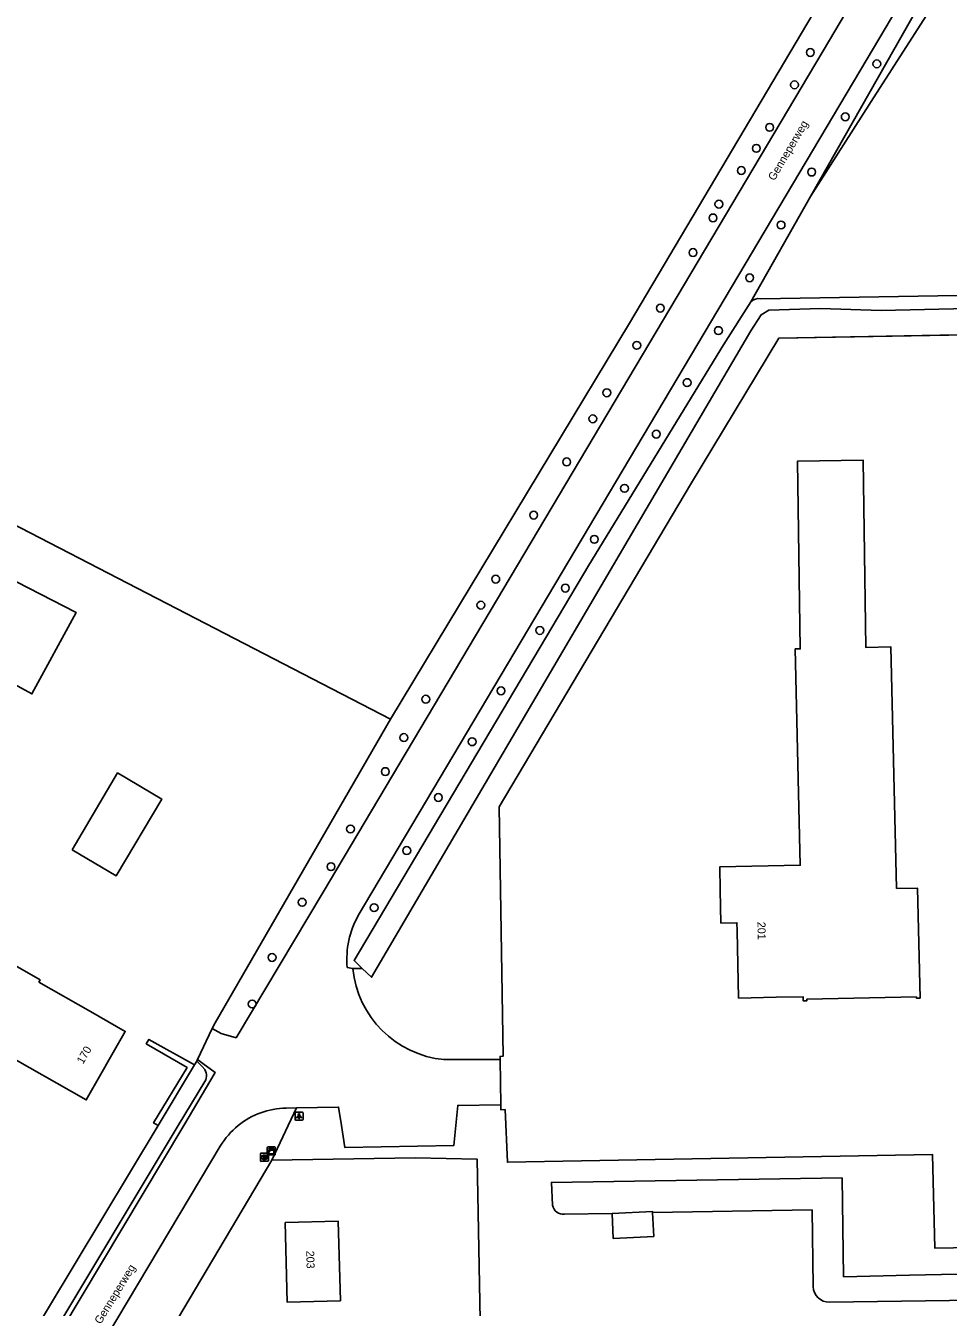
# Model space of a CAD drawing. Extents: x 160203 to 161526, y 379529 to 381797.
# Drawn here: x 160351.6 to 160466.9, y 379977.3 to 380137.4 of the extents above; entities that cross this region are included whole.
import ezdxf

# ---------------------------------------------------------------- set-up
doc = ezdxf.new("R2010")
doc.units = 0
for name, color, linetype in [('IMGEO_Berm_groen', 7, 'Continuous'), ('IMGEO_Boom', 7, 'Continuous'), ('IMGEO_Bouwland', 7, 'Continuous'), ('IMGEO_Grasland_agrarisch', 7, 'Continuous'), ('IMGEO_Grasland_overig', 7, 'Continuous'), ('IMGEO_Groenvoorziening', 7, 'Continuous'), ('IMGEO_Haag', 7, 'Continuous'), ('IMGEO_Hek', 7, 'Continuous'), ('IMGEO_Kast', 7, 'Continuous'), ('IMGEO_Lichtpunt', 7, 'Continuous'), ('IMGEO_Openbare_ruimte_label', 7, 'Continuous'), ('IMGEO_Pand', 7, 'Continuous'), ('IMGEO_Pand_nummerreeks', 7, 'Continuous'), ('IMGEO_Rijbaan_lokaal_open', 7, 'Continuous'), ('IMGEO_Rioolput', 7, 'Continuous'), ('IMGEO_Waterloop', 7, 'Continuous')]:
    doc.layers.add(name, color=color, linetype=linetype)

msp = doc.modelspace()

# ---------------------------------------------------------------- linework, layer by layer
at = {"layer": 'IMGEO_Berm_groen'}
for points in [[(160373.06, 380008.26), (160372.96, 380008.04)], [(160382.33, 379995.65), (160385.42, 380002.19)], [(160360.33, 379958.58), (160382.33, 379995.65)]]:
    msp.add_lwpolyline(points, dxfattribs=at)
at = {"layer": 'IMGEO_Boom'}
for centre in [(160449.64, 380134.09), (160457.95, 380132.66), (160447.66, 380130.04), (160454, 380126.05), (160444.56, 380124.73), (160442.89, 380122.1), (160441.01, 380119.33), (160449.81, 380119.14), (160438.21, 380115.13), (160437.47, 380113.41), (160445.98, 380112.53), (160434.98, 380109.08), (160442.05, 380105.93), (160430.89, 380102.14), (160438.15, 380099.33), (160427.95, 380097.48), (160434.24, 380092.83), (160424.2, 380091.56), (160422.45, 380088.31), (160430.38, 380086.39), (160419.19, 380082.92), (160426.41, 380079.61), (160415.06, 380076.27), (160422.64, 380073.24), (160410.32, 380068.27), (160419.01, 380067.15), (160408.46, 380065.02), (160415.83, 380061.86), (160401.58, 380053.26), (160410.98, 380054.31), (160398.84, 380048.47), (160407.37, 380047.95), (160396.52, 380044.22), (160403.14, 380040.98), (160392.17, 380037.05), (160399.2, 380034.35), (160389.73, 380032.34), (160386.13, 380027.89), (160395.12, 380027.22), (160382.37, 380020.99), (160379.88, 380015.17)]:
    msp.add_circle(centre, 0.489, dxfattribs=at)
at = {"layer": 'IMGEO_Bouwland'}
msp.add_lwpolyline([(160442.2, 380102.92), (160449.65, 380116.07)], dxfattribs=at)
at = {"layer": 'IMGEO_Grasland_agrarisch'}
for points in [[(160457.16, 380151.09), (160427.02, 380100.25), (160397.18, 380050.75)], [(160397.18, 380050.75), (160349.7, 380075.29)]]:
    msp.add_lwpolyline(points, dxfattribs=at)
at = {"layer": 'IMGEO_Grasland_overig'}
for points in [[(160449.65, 380116.07), (160457.26, 380127.95), (160486.32, 380173.3), (160489.77, 380174.54)], [(160449.65, 380116.07), (160465.43, 380143.93), (160472.15, 380155.79)], [(160497.32, 380099.25), (160500, 380099.36), (160552.52, 380100.27), (160568.93, 380078.16), (160570.15, 380000), (160570.38, 379986.91), (160500, 379985.28), (160465.21, 379984.65), (160464.91, 379996.35), (160411.77, 379995.39), (160411.48, 380001.98), (160410.95, 380001.97), (160410.94, 380002.59)], [(160410.88, 380008.24), (160410.87, 380008.63), (160411.24, 380008.64), (160410.76, 380039.8), (160434.65, 380080.09), (160445.7, 380098.4), (160492.69, 380099.27)], [(160392.47, 380019.6), (160393.64, 380019.61)], [(160368.22, 379945.15), (160400.15, 379946.25), (160408.91, 379946.67), (160407.99, 379995.8), (160400.24, 379995.97), (160382.33, 379995.65)]]:
    msp.add_lwpolyline(points, dxfattribs=at)
at = {"layer": 'IMGEO_Groenvoorziening'}
msp.add_lwpolyline([(160397.18, 380050.75), (160375.24, 380012.84), (160374.9, 380012.13)], dxfattribs=at)
at = {"layer": 'IMGEO_Haag'}
msp.add_lwpolyline([(160368.12, 380000), (160367.56, 380000.32), (160371.74, 380007.24), (160366.65, 380010.21), (160366.97, 380010.76), (160372.68, 380007.58)], dxfattribs=at)
at = {"layer": 'IMGEO_Hek'}
for points in [[(160500, 380099.36), (160445.7, 380098.4)], [(160445.7, 380098.4), (160434.65, 380080.09), (160410.76, 380039.8), (160411.24, 380008.64)], [(160397.18, 380050.75), (160349.7, 380075.29)], [(160411.48, 380001.98), (160411.77, 379995.39)], [(160411.77, 379995.39), (160464.91, 379996.35), (160465.21, 379984.65), (160500, 379985.28)]]:
    msp.add_lwpolyline(points, dxfattribs=at)
at = {"layer": 'IMGEO_Kast'}
for p, q in [((160381.77, 379996.39), (160381.77, 379997.23)), ((160381.77, 379997.23), (160381.77, 379996.39)), ((160381.85, 379997.31), (160382.69, 379997.31)), ((160382.69, 379997.31), (160381.85, 379997.31)), ((160382.7, 379996.31), (160381.86, 379996.31)), ((160381.86, 379996.31), (160382.7, 379996.31)), ((160382.77, 379997.24), (160382.77, 379996.4)), ((160382.77, 379996.4), (160382.77, 379997.24))]:
    msp.add_line(p, q, dxfattribs=at)
for points in [[(160381.97, 379997.1), (160382.57, 379997.1), (160382.57, 379997.02), (160381.97, 379997.02), (160381.97, 379997.1)], [(160381.97, 379996.93), (160382.57, 379996.93), (160382.57, 379996.44), (160381.97, 379996.44), (160381.97, 379996.93)]]:
    msp.add_lwpolyline(points, dxfattribs=at)
msp.add_circle((160382.05, 379996.78), 0.0377, dxfattribs=at)
for centre, start, end in [((160381.85, 379997.24), 92.4484, 184.2845), ((160381.85, 379997.24), 92.4484, 184.2845), ((160381.85, 379996.39), 182.4484, 274.2845), ((160381.85, 379996.39), 182.4484, 274.2845), ((160382.69, 379997.24), 2.4484, 94.2845), ((160382.69, 379997.24), 2.4484, 94.2845), ((160382.69, 379996.39), 272.4484, 4.2845), ((160382.69, 379996.39), 272.4484, 4.2845)]:
    msp.add_arc(centre, 0.0779, start, end, dxfattribs=at)
at = {"layer": 'IMGEO_Lichtpunt'}
for p, q in [((160385.24, 380001.56), (160385.24, 380000.75)), ((160385.24, 380001.56), (160385.24, 380000.75)), ((160386.14, 380001.65), (160385.34, 380001.65)), ((160386.14, 380001.65), (160385.34, 380001.65)), ((160386.24, 380000.75), (160386.24, 380001.56)), ((160386.24, 380000.75), (160386.24, 380001.56)), ((160385.34, 380000.66), (160386.14, 380000.66)), ((160385.34, 380000.66), (160386.14, 380000.66))]:
    msp.add_line(p, q, dxfattribs=at)
for points in [[(160385.62, 380001.22), (160385.65, 380001.19), (160385.47, 380000.93), (160385.43, 380000.96), (160385.62, 380001.22)], [(160385.72, 380001.17), (160385.76, 380001.17), (160385.76, 380000.85), (160385.72, 380000.85), (160385.72, 380001.17)], [(160385.83, 380001.19), (160385.87, 380001.22), (160386.05, 380000.96), (160386.01, 380000.93), (160385.83, 380001.19)]]:
    msp.add_lwpolyline(points, dxfattribs=at)
msp.add_circle((160385.74, 380001.36), 0.0994, dxfattribs=at)
for centre, start, end in [((160385.34, 380001.56), 90, 180), ((160385.34, 380001.56), 90, 180), ((160386.14, 380001.56), 0, 90), ((160386.14, 380001.56), 0, 90), ((160385.34, 380000.75), 180, 270), ((160385.34, 380000.75), 180, 270), ((160386.14, 380000.75), 270, 0), ((160386.14, 380000.75), 270, 360)]:
    msp.add_arc(centre, 0.0946, start, end, dxfattribs=at)
at = {"layer": 'IMGEO_Pand'}
for points in [[(160460.39, 380029.6), (160463.04, 380029.65), (160463.35, 380015.92), (160462.89, 380015.91), (160462.89, 380016.07), (160449.18, 380015.77), (160449.19, 380015.57), (160448.75, 380015.56), (160448.74, 380016.09), (160445.35, 380016.01), (160440.68, 380015.91), (160440.49, 380024.3), (160440.47, 380025.32), (160438.47, 380025.28), (160438.37, 380029.41), (160438.31, 380032.3), (160448.37, 380032.52), (160447.76, 380059.54), (160448.38, 380059.55), (160448.05, 380083.02), (160456.23, 380083.14), (160456.56, 380059.73), (160459.71, 380059.8), (160460.39, 380029.6)], [(160343.54, 380058.71), (160348.96, 380068.69), (160357.89, 380064.08), (160352.36, 380053.92), (160343.54, 380058.71)], [(160357.37, 380034.45), (160363.05, 380044.05), (160368.57, 380040.78), (160362.88, 380031.19), (160357.37, 380034.45)], [(160353.21, 380017.9), (160353.37, 380018.19), (160345.85, 380022.48), (160340.67, 380025.43), (160335.52, 380028.43), (160333.9, 380025.59), (160330.26, 380019.22), (160334.94, 380016.55), (160333.95, 380014.81), (160332.42, 380015.68), (160331.47, 380014.01), (160343.62, 380007.08), (160346.29, 380005.56), (160348.42, 380009.29), (160359.14, 380003.18), (160364.02, 380011.74), (160359.68, 380014.22), (160353.21, 380017.9)], [(160390.9, 379978.09), (160384.27, 379977.91), (160384.01, 379987.85), (160390.64, 379988.02), (160390.9, 379978.09)], [(160424.87, 379989), (160429.92, 379989.24), (160429.93, 379989.1)], [(160429.93, 379989.1), (160430.07, 379986.13), (160425.01, 379985.89), (160424.87, 379989)]]:
    msp.add_lwpolyline(points, dxfattribs=at)
at = {"layer": 'IMGEO_Rijbaan_lokaal_open'}
for points in [[(160457.51, 380144.89), (160452.03, 380135.62), (160388.75, 380029.17), (160377.87, 380010.95), (160375.99, 380011.51), (160374.9, 380012.13)], [(160462.03, 380142.26), (160456.74, 380133.28), (160393.14, 380026.24)], [(160391.75, 380019.75), (160392.47, 380019.6)], [(160374.9, 380012.13), (160373.06, 380008.26)], [(160353.43, 379970.05), (160371.33, 380000), (160375.27, 380006.61), (160373.71, 380007.73), (160373.06, 380008.26)], [(160410.88, 380008.24), (160403.85, 380008.23)], [(160410.94, 380002.59), (160410.88, 380008.24)], [(160385.42, 380002.19), (160390.68, 380002.3), (160391.04, 380000), (160391.47, 379997.23), (160405.09, 379997.51), (160405.33, 380000), (160405.58, 380002.5), (160410.94, 380002.59)], [(160385.42, 380002.19), (160384.12, 380002.17)], [(160375.89, 379997.42), (160357.91, 379967.3)]]:
    msp.add_lwpolyline(points, dxfattribs=at)
for centre, radius, start, end in [((160402.99, 380020.75), 11.28, 150.8511, 185.0979), ((160405.04, 380020.8), 12.63, 185.4693, 264.6113), ((160384.29, 379992.35), 9.82, 91.0157, 128.8336), ((160384.33, 379992.35), 9.84, 129.0059, 149.0134)]:
    msp.add_arc(centre, radius, start, end, dxfattribs=at)
at = {"layer": 'IMGEO_Rioolput'}
for p, q in [((160380.91, 379995.59), (160380.91, 379996.44)), ((160380.98, 379996.52), (160381.84, 379996.52)), ((160381.4, 379996.3), (160381.42, 379996.3)), ((160381.91, 379996.44), (160381.91, 379995.59)), ((160381.84, 379995.52), (160380.98, 379995.52)), ((160381.42, 379995.74), (160381.4, 379995.74))]:
    msp.add_line(p, q, dxfattribs=at)
for points in [[(160380.91, 379995.59), (160380.91, 379996.44)], [(160380.98, 379996.52), (160381.84, 379996.52)], [(160381.5, 379996.21), (160381.25, 379996.22), (160381.25, 379995.82)], [(160381.43, 379996.14), (160381.37, 379996.14), (160381.37, 379996.05)], [(160381.37, 379996.05), (160381.42, 379996.05)], [(160381.91, 379996.44), (160381.91, 379995.59)], [(160381.84, 379995.52), (160380.98, 379995.52)], [(160381.25, 379995.82), (160381.37, 379995.82), (160381.37, 379995.98), (160381.38, 379995.98)], [(160381.43, 379995.95), (160381.5, 379995.82), (160381.64, 379995.82), (160381.57, 379995.94)]]:
    msp.add_lwpolyline(points, dxfattribs=at)
for centre, radius, start, end in [((160380.99, 379996.44), 0.0765, 91.552, 178.448), ((160380.99, 379996.44), 0.0765, 91.552, 178.448), ((160381.41, 379996.24), 0.19, 274.7715, 282.9687), ((160381.43, 379996.04), 0.0964, 77.0061, 93.1865), ((160381.45, 379996.1), 0.0378, 276.6634, 79.6772), ((160381.5, 379996.11), 0.109, 350.3612, 89.416), ((160381.5, 379996.1), 0.112, 277.5842, 350.9817), ((160381.83, 379996.44), 0.0765, 1.552, 88.448), ((160381.83, 379996.44), 0.0765, 1.552, 88.448), ((160380.99, 379995.59), 0.0765, 181.552, 268.448), ((160380.99, 379995.59), 0.0765, 181.552, 268.448), ((160381.38, 379995.93), 0.0533, 26.0293, 88.6989), ((160381.48, 379995.89), 0.108, 29.5134, 73.7905), ((160381.83, 379995.59), 0.0765, 271.552, 358.448), ((160381.83, 379995.59), 0.0765, 271.552, 358.448)]:
    msp.add_arc(centre, radius, start, end, dxfattribs=at)
for centre, major_axis, ratio, start_param, end_param in [((160381.4, 379996.02), (-0.387, 0.002), 0.722429, 4.712389, 7.853982), ((160381.42, 379996.02), (-0.39, 0.002), 0.717154, 1.570796, 4.712389)]:
    msp.add_ellipse(centre, major_axis=major_axis, ratio=ratio, start_param=start_param, end_param=end_param, dxfattribs=at)
at = {"layer": 'IMGEO_Waterloop'}
for points in [[(160552.79, 380106.07), (160552.5, 380105.98), (160542.34, 380104.96), (160500, 380104.25), (160443.43, 380103.3)], [(160572.68, 380044.44), (160571.3, 380082.02), (160570.87, 380083.04), (160564.09, 380090.73), (160556.2, 380100.44), (160553.48, 380103.35), (160548.27, 380103.87), (160500, 380102.78), (160458.47, 380101.85), (160450.92, 380102.08), (160444.44, 380101.9), (160443.49, 380101.31), (160442.22, 380099.32), (160394.8, 380018.51), (160393.64, 380019.61)], [(160393.64, 380019.61), (160392.61, 380020.6), (160421.94, 380070), (160438.79, 380097.57), (160442.2, 380102.92)], [(160417.41, 379990.03), (160417.28, 379992.88), (160453.6, 379993.44), (160453.79, 379981.09), (160462.01, 379981.27), (160500, 379982.1), (160572.95, 379983.71), (160572.74, 380000), (160572.54, 380019.05), (160573.09, 380019.94), (160574.06, 380020.32), (160587.13, 380020.56)], [(160372.68, 380007.58), (160368.12, 380000)], [(160372.96, 380008.04), (160372.68, 380007.58)], [(160372.96, 380008.04), (160373.8, 380007.18)], [(160373.96, 380005.5), (160370.65, 380000), (160353.95, 379972.21)], [(160368.12, 380000), (160350.83, 379971.26), (160350.52, 379971.11), (160350.09, 379971.23), (160347.92, 379974.93), (160340.63, 379986.39), (160337.45, 379991.38)], [(160424.87, 379989), (160418.92, 379988.92)], [(160450, 379979.87), (160449.85, 379989.44), (160429.93, 379989.1)], [(160576.07, 379979.7), (160500, 379978.6), (160458.03, 379977.99), (160452.03, 379977.91)]]:
    msp.add_lwpolyline(points, dxfattribs=at)
for centre, radius, start, end in [((160443.18, 380101.96), 1.37, 79.4379, 135.4881), ((160372.9, 380006.25), 1.29, 324.7863, 45.9847), ((160418.76, 379990.27), 1.37, 190.2348, 277.0146), ((160452, 379979.91), 2, 180.9094, 270.782)]:
    msp.add_arc(centre, radius, start, end, dxfattribs=at)

# ---------------------------------------------------------------- texts
at = {"layer": 'IMGEO_Openbare_ruimte_label'}
for rotation, p in [(59.4096, (160445.14, 380117.98)), (58.4563, (160360.95, 379975.09))]:
    msp.add_text('Genneperweg', height=1, rotation=rotation, dxfattribs=at).set_placement(p)
at = {"layer": 'IMGEO_Pand_nummerreeks'}
for s, rotation, p in [('201', 270.998, (160443.03, 380025.44)), ('170', 60.3153, (160358.75, 380007.6)), ('203', 271.505, (160386.63, 379984.33))]:
    msp.add_text(s, height=1, rotation=rotation, dxfattribs=at).set_placement(p)

doc.saveas('drawing.dxf')
